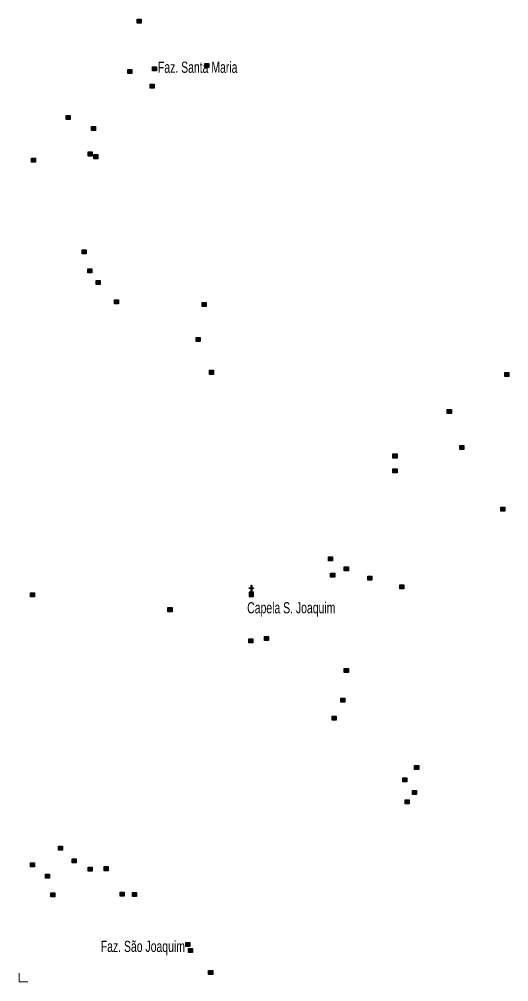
# Model space of a CAD drawing. Extents: x 447.8 to 473.9, y 7733.1 to 7760.8.
# Drawn here: x 447.86 to 451.37, y 7733.07 to 7739.97 of the extents above; entities that cross this region are included whole.
import ezdxf
from ezdxf.enums import TextEntityAlignment as Align

# ---------------------------------------------------------------- set-up
doc = ezdxf.new("R2010")
doc.units = 0
doc.header["$LTSCALE"] = 0.032
for name, color, linetype, lineweight in [('2', 7, 'Continuous', 25), ('6', 7, 'Continuous', 25), ('63', 7, 'Continuous', 13)]:
    doc.layers.add(name, color=color, linetype=linetype, lineweight=lineweight)
doc.layers.add('61', color=7, linetype='Continuous')

msp = doc.modelspace()

# ---------------------------------------------------------------- hatches: boundary and pattern name
at = {"layer": '2'}
for points in [[(448.7068, 7739.9733), (448.7358, 7739.9733), (448.7358, 7739.9443), (448.7068, 7739.9443)], [(448.6386, 7739.6134), (448.6676, 7739.6134), (448.6676, 7739.5844), (448.6386, 7739.5844)], [(448.8158, 7739.6325), (448.8448, 7739.6325), (448.8448, 7739.6035), (448.8158, 7739.6035)], [(449.1924, 7739.6557), (449.2214, 7739.6557), (449.2214, 7739.6267), (449.1924, 7739.6267)], [(448.7995, 7739.5071), (448.8285, 7739.5071), (448.8285, 7739.4781), (448.7995, 7739.4781)], [(448.1969, 7739.2835), (448.2259, 7739.2835), (448.2259, 7739.2545), (448.1969, 7739.2545)], [(448.3796, 7739.2045), (448.4086, 7739.2045), (448.4086, 7739.1755), (448.3796, 7739.1755)], [(448.355, 7739.0218), (448.384, 7739.0218), (448.384, 7738.9928), (448.355, 7738.9928)], [(448.3959, 7739.0027), (448.4249, 7739.0027), (448.4249, 7738.9737), (448.3959, 7738.9737)], [(447.9488, 7738.9782), (447.9778, 7738.9782), (447.9778, 7738.9492), (447.9488, 7738.9492)], [(448.3114, 7738.3211), (448.3404, 7738.3211), (448.3404, 7738.2921), (448.3114, 7738.2921)], [(448.3523, 7738.1848), (448.3813, 7738.1848), (448.3813, 7738.1558), (448.3523, 7738.1558)], [(448.4123, 7738.1003), (448.4413, 7738.1003), (448.4413, 7738.0713), (448.4123, 7738.0713)], [(448.5432, 7737.9612), (448.5722, 7737.9612), (448.5722, 7737.9322), (448.5432, 7737.9322)], [(449.173, 7737.9421), (449.202, 7737.9421), (449.202, 7737.9131), (449.173, 7737.9131)], [(449.1293, 7737.6913), (449.1583, 7737.6913), (449.1583, 7737.6623), (449.1293, 7737.6623)], [(449.2248, 7737.4568), (449.2538, 7737.4568), (449.2538, 7737.4278), (449.2248, 7737.4278)], [(451.3432, 7737.4405), (451.3722, 7737.4405), (451.3722, 7737.4115), (451.3432, 7737.4115)], [(450.9315, 7737.176), (450.9605, 7737.176), (450.9605, 7737.147), (450.9315, 7737.147)], [(450.5416, 7736.857), (450.5706, 7736.857), (450.5706, 7736.828), (450.5416, 7736.828)], [(451.0215, 7736.917), (451.0505, 7736.917), (451.0505, 7736.888), (451.0215, 7736.888)], [(450.5416, 7736.7507), (450.5706, 7736.7507), (450.5706, 7736.7217), (450.5416, 7736.7217)], [(451.3159, 7736.4753), (451.3449, 7736.4753), (451.3449, 7736.4463), (451.3159, 7736.4463)], [(450.0781, 7736.1209), (450.1071, 7736.1209), (450.1071, 7736.0919), (450.0781, 7736.0919)], [(450.1926, 7736.0473), (450.2216, 7736.0473), (450.2216, 7736.0183), (450.1926, 7736.0183)], [(450.0945, 7736.0037), (450.1235, 7736.0037), (450.1235, 7735.9747), (450.0945, 7735.9747)], [(450.3617, 7735.9818), (450.3907, 7735.9818), (450.3907, 7735.9528), (450.3617, 7735.9528)], [(450.5907, 7735.9191), (450.6197, 7735.9191), (450.6197, 7735.8901), (450.5907, 7735.8901)], [(447.9406, 7735.8619), (447.9696, 7735.8619), (447.9696, 7735.8329), (447.9406, 7735.8329)], [(448.9276, 7735.7556), (448.9566, 7735.7556), (448.9566, 7735.7266), (448.9276, 7735.7266)], [(449.6201, 7735.5483), (449.6491, 7735.5483), (449.6491, 7735.5193), (449.6201, 7735.5193)], [(449.5083, 7735.532), (449.5373, 7735.532), (449.5373, 7735.503), (449.5083, 7735.503)], [(450.1926, 7735.3193), (450.2216, 7735.3193), (450.2216, 7735.2903), (450.1926, 7735.2903)], [(450.1681, 7735.1067), (450.1971, 7735.1067), (450.1971, 7735.0777), (450.1681, 7735.0777)], [(450.1054, 7734.9785), (450.1344, 7734.9785), (450.1344, 7734.9495), (450.1054, 7734.9495)], [(450.697, 7734.6241), (450.726, 7734.6241), (450.726, 7734.5951), (450.697, 7734.5951)], [(450.6125, 7734.5368), (450.6415, 7734.5368), (450.6415, 7734.5078), (450.6125, 7734.5078)], [(450.6807, 7734.4442), (450.7097, 7734.4442), (450.7097, 7734.4152), (450.6807, 7734.4152)], [(450.6289, 7734.3787), (450.6579, 7734.3787), (450.6579, 7734.3497), (450.6289, 7734.3497)], [(448.1424, 7734.0461), (448.1714, 7734.0461), (448.1714, 7734.0171), (448.1424, 7734.0171)], [(448.2405, 7733.9561), (448.2695, 7733.9561), (448.2695, 7733.9271), (448.2405, 7733.9271)], [(447.9406, 7733.9261), (447.9696, 7733.9261), (447.9696, 7733.8971), (447.9406, 7733.8971)], [(448.355, 7733.8961), (448.384, 7733.8961), (448.384, 7733.8671), (448.355, 7733.8671)], [(448.4696, 7733.8989), (448.4986, 7733.8989), (448.4986, 7733.8699), (448.4696, 7733.8699)], [(448.0497, 7733.8443), (448.0787, 7733.8443), (448.0787, 7733.8153), (448.0497, 7733.8153)], [(448.0879, 7733.7107), (448.1169, 7733.7107), (448.1169, 7733.6817), (448.0879, 7733.6817)], [(448.5841, 7733.7162), (448.6131, 7733.7162), (448.6131, 7733.6872), (448.5841, 7733.6872)], [(448.674, 7733.7135), (448.703, 7733.7135), (448.703, 7733.6845), (448.674, 7733.6845)], [(449.0557, 7733.3563), (449.0847, 7733.3563), (449.0847, 7733.3273), (449.0557, 7733.3273)], [(449.0748, 7733.3127), (449.1038, 7733.3127), (449.1038, 7733.2837), (449.0748, 7733.2837)], [(449.2193, 7733.1546), (449.2483, 7733.1546), (449.2483, 7733.1256), (449.2193, 7733.1256)]]:
    msp.add_hatch(color=256, dxfattribs=at).paths.add_polyline_path(points)
at = {"layer": '6'}
for points in [[(449.5287, 7735.8659), (449.5237, 7735.8659), (449.5237, 7735.8934), (449.5112, 7735.8934), (449.5112, 7735.8984), (449.5237, 7735.8984), (449.5237, 7735.9159), (449.5287, 7735.9159), (449.5287, 7735.8984), (449.5412, 7735.8984), (449.5412, 7735.8934), (449.5287, 7735.8934)], [(449.5112, 7735.8659), (449.5112, 7735.8359), (449.5412, 7735.8359), (449.5412, 7735.8659)]]:
    msp.add_hatch(color=256, dxfattribs=at).paths.add_polyline_path(points)

# ---------------------------------------------------------------- linework, layer by layer
at = {"layer": '2'}
for points in [[(448.7068, 7739.9733), (448.7358, 7739.9733), (448.7358, 7739.9443), (448.7068, 7739.9443)], [(448.6386, 7739.6134), (448.6676, 7739.6134), (448.6676, 7739.5844), (448.6386, 7739.5844)], [(448.8158, 7739.6325), (448.8448, 7739.6325), (448.8448, 7739.6035), (448.8158, 7739.6035)], [(449.1924, 7739.6557), (449.2214, 7739.6557), (449.2214, 7739.6267), (449.1924, 7739.6267)], [(448.7995, 7739.5071), (448.8285, 7739.5071), (448.8285, 7739.4781), (448.7995, 7739.4781)], [(448.1969, 7739.2835), (448.2259, 7739.2835), (448.2259, 7739.2545), (448.1969, 7739.2545)], [(448.3796, 7739.2045), (448.4086, 7739.2045), (448.4086, 7739.1755), (448.3796, 7739.1755)], [(448.355, 7739.0218), (448.384, 7739.0218), (448.384, 7738.9928), (448.355, 7738.9928)], [(448.3959, 7739.0027), (448.4249, 7739.0027), (448.4249, 7738.9737), (448.3959, 7738.9737)], [(447.9488, 7738.9782), (447.9778, 7738.9782), (447.9778, 7738.9492), (447.9488, 7738.9492)], [(448.3114, 7738.3211), (448.3404, 7738.3211), (448.3404, 7738.2921), (448.3114, 7738.2921)], [(448.3523, 7738.1848), (448.3813, 7738.1848), (448.3813, 7738.1558), (448.3523, 7738.1558)], [(448.4123, 7738.1003), (448.4413, 7738.1003), (448.4413, 7738.0713), (448.4123, 7738.0713)], [(448.5432, 7737.9612), (448.5722, 7737.9612), (448.5722, 7737.9322), (448.5432, 7737.9322)], [(449.173, 7737.9421), (449.202, 7737.9421), (449.202, 7737.9131), (449.173, 7737.9131)], [(449.1293, 7737.6913), (449.1583, 7737.6913), (449.1583, 7737.6623), (449.1293, 7737.6623)], [(449.2248, 7737.4568), (449.2538, 7737.4568), (449.2538, 7737.4278), (449.2248, 7737.4278)], [(451.3432, 7737.4405), (451.3722, 7737.4405), (451.3722, 7737.4115), (451.3432, 7737.4115)], [(450.9315, 7737.176), (450.9605, 7737.176), (450.9605, 7737.147), (450.9315, 7737.147)], [(450.5416, 7736.857), (450.5706, 7736.857), (450.5706, 7736.828), (450.5416, 7736.828)], [(451.0215, 7736.917), (451.0505, 7736.917), (451.0505, 7736.888), (451.0215, 7736.888)], [(450.5416, 7736.7507), (450.5706, 7736.7507), (450.5706, 7736.7217), (450.5416, 7736.7217)], [(451.3159, 7736.4753), (451.3449, 7736.4753), (451.3449, 7736.4463), (451.3159, 7736.4463)], [(450.0781, 7736.1209), (450.1071, 7736.1209), (450.1071, 7736.0919), (450.0781, 7736.0919)], [(450.1926, 7736.0473), (450.2216, 7736.0473), (450.2216, 7736.0183), (450.1926, 7736.0183)], [(450.0945, 7736.0037), (450.1235, 7736.0037), (450.1235, 7735.9747), (450.0945, 7735.9747)], [(450.3617, 7735.9818), (450.3907, 7735.9818), (450.3907, 7735.9528), (450.3617, 7735.9528)], [(450.5907, 7735.9191), (450.6197, 7735.9191), (450.6197, 7735.8901), (450.5907, 7735.8901)], [(447.9406, 7735.8619), (447.9696, 7735.8619), (447.9696, 7735.8329), (447.9406, 7735.8329)], [(448.9276, 7735.7556), (448.9566, 7735.7556), (448.9566, 7735.7266), (448.9276, 7735.7266)], [(449.6201, 7735.5483), (449.6491, 7735.5483), (449.6491, 7735.5193), (449.6201, 7735.5193)], [(449.5083, 7735.532), (449.5373, 7735.532), (449.5373, 7735.503), (449.5083, 7735.503)], [(450.1926, 7735.3193), (450.2216, 7735.3193), (450.2216, 7735.2903), (450.1926, 7735.2903)], [(450.1681, 7735.1067), (450.1971, 7735.1067), (450.1971, 7735.0777), (450.1681, 7735.0777)], [(450.1054, 7734.9785), (450.1344, 7734.9785), (450.1344, 7734.9495), (450.1054, 7734.9495)], [(450.697, 7734.6241), (450.726, 7734.6241), (450.726, 7734.5951), (450.697, 7734.5951)], [(450.6125, 7734.5368), (450.6415, 7734.5368), (450.6415, 7734.5078), (450.6125, 7734.5078)], [(450.6807, 7734.4442), (450.7097, 7734.4442), (450.7097, 7734.4152), (450.6807, 7734.4152)], [(450.6289, 7734.3787), (450.6579, 7734.3787), (450.6579, 7734.3497), (450.6289, 7734.3497)], [(448.1424, 7734.0461), (448.1714, 7734.0461), (448.1714, 7734.0171), (448.1424, 7734.0171)], [(448.2405, 7733.9561), (448.2695, 7733.9561), (448.2695, 7733.9271), (448.2405, 7733.9271)], [(447.9406, 7733.9261), (447.9696, 7733.9261), (447.9696, 7733.8971), (447.9406, 7733.8971)], [(448.355, 7733.8961), (448.384, 7733.8961), (448.384, 7733.8671), (448.355, 7733.8671)], [(448.4696, 7733.8989), (448.4986, 7733.8989), (448.4986, 7733.8699), (448.4696, 7733.8699)], [(448.0497, 7733.8443), (448.0787, 7733.8443), (448.0787, 7733.8153), (448.0497, 7733.8153)], [(448.0879, 7733.7107), (448.1169, 7733.7107), (448.1169, 7733.6817), (448.0879, 7733.6817)], [(448.5841, 7733.7162), (448.6131, 7733.7162), (448.6131, 7733.6872), (448.5841, 7733.6872)], [(448.674, 7733.7135), (448.703, 7733.7135), (448.703, 7733.6845), (448.674, 7733.6845)], [(449.0557, 7733.3563), (449.0847, 7733.3563), (449.0847, 7733.3273), (449.0557, 7733.3273)], [(449.0748, 7733.3127), (449.1038, 7733.3127), (449.1038, 7733.2837), (449.0748, 7733.2837)], [(449.2193, 7733.1546), (449.2483, 7733.1546), (449.2483, 7733.1256), (449.2193, 7733.1256)]]:
    msp.add_lwpolyline(points, close=True, dxfattribs=at)
at = {"layer": '6'}
for points in [[(449.5287, 7735.8659), (449.5237, 7735.8659), (449.5237, 7735.8934), (449.5112, 7735.8934), (449.5112, 7735.8984), (449.5237, 7735.8984), (449.5237, 7735.9159), (449.5287, 7735.9159), (449.5287, 7735.8984), (449.5412, 7735.8984), (449.5412, 7735.8934), (449.5287, 7735.8934)], [(449.5112, 7735.8659), (449.5112, 7735.8359), (449.5412, 7735.8359), (449.5412, 7735.8659)]]:
    msp.add_lwpolyline(points, close=True, dxfattribs=at)
at = {"layer": '63'}
msp.add_lwpolyline([(447.8608, 7733.1355), (447.8608, 7733.0739), (447.9215, 7733.0739)], dxfattribs=at)

# ---------------------------------------------------------------- texts
at = {"layer": '61', "width": 0.7}
for s, p in [('Faz. Santa Maria', (448.8559, 7739.5893)), ('Capela S. Joaquim', (449.4958, 7735.7146))]:
    msp.add_text(s, height=0.08, dxfattribs=at).set_placement(p)
msp.add_text('Faz. São Joaquim', height=0.08, dxfattribs=at).set_placement((449.0493, 7733.2874), align=Align.RIGHT)

doc.saveas('drawing.dxf')
